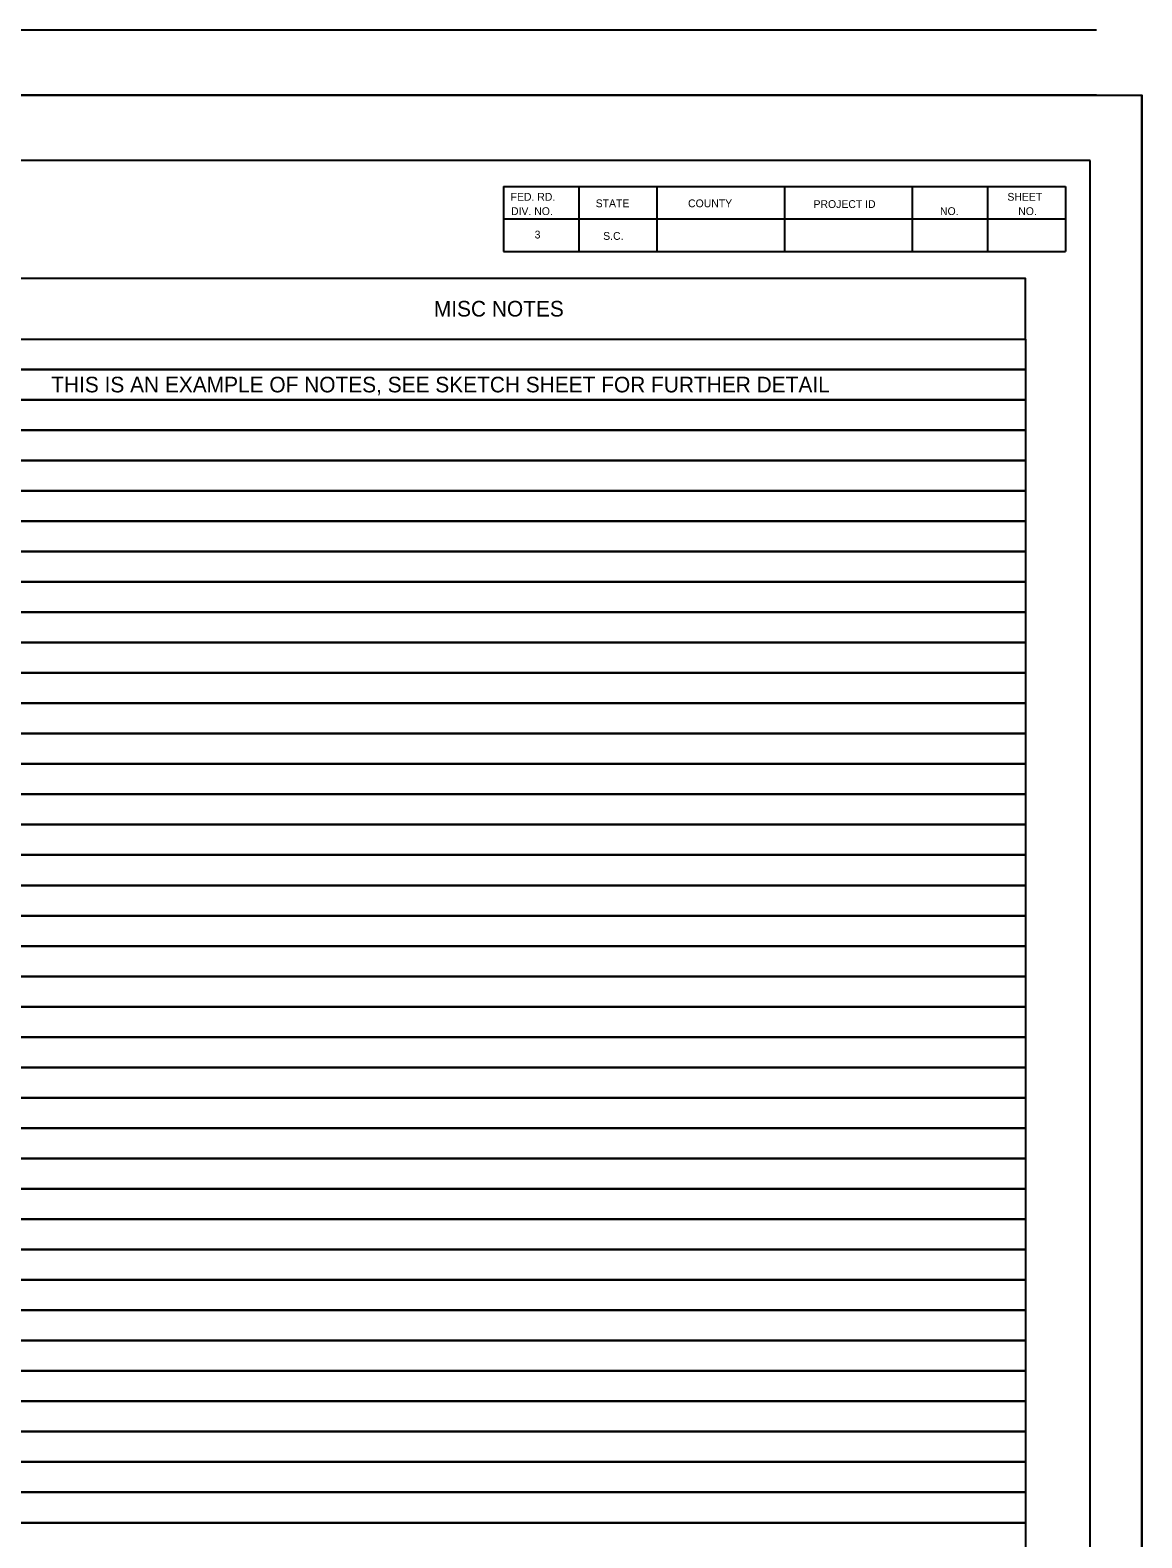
# Model space of a CAD drawing. Extents: x 14330 to 16126, y 15844 to 16994.
# Drawn here: x 15699 to 16126, y 16415 to 16994 of the extents above; entities that cross this region are included whole.
import ezdxf

# ---------------------------------------------------------------- set-up
doc = ezdxf.new("R2010")
doc.units = 0
for name, color, linetype in [('RD_SHT_Bndy', 7, 'Continuous'), ('RD_SHT_Iplotshp', 7, 'Continuous'), ('RD_SHT_Snap', 7, 'Continuous'), ('RD_SHT_TX', 7, 'Continuous')]:
    doc.layers.add(name, color=color, linetype=linetype)

msp = doc.modelspace()

# ---------------------------------------------------------------- linework, layer by layer
at = {"layer": 'RD_SHT_Bndy'}
for p, q in [((16108.25, 16993.63), (14348.25, 16993.63)), ((16108.25, 16968.63), (14348.25, 16968.63)), ((16105.85, 16943.63), (14430.85, 16943.63)), ((16105.85, 15893.63), (16105.85, 16943.63)), ((15880.35, 16933.63), (15880.35, 16908.63)), ((15880.35, 16933.63), (16037.35, 16933.63)), ((15909.35, 16933.63), (15909.35, 16908.63)), ((15939.35, 16933.63), (15939.35, 16908.63)), ((15988.35, 16933.63), (15988.35, 16908.63)), ((16037.35, 16933.63), (16037.35, 16908.63)), ((16037.35, 16933.63), (16096.35, 16933.63)), ((16066.35, 16933.63), (16066.35, 16908.63)), ((16096.35, 16933.63), (16096.35, 16908.63)), ((15880.35, 16921.13), (16037.35, 16921.13)), ((16037.35, 16921.13), (16096.35, 16921.13)), ((15880.35, 16908.63), (16037.35, 16908.63)), ((16037.35, 16908.63), (16096.35, 16908.63))]:
    msp.add_line(p, q, dxfattribs=at)
for points in [[(15676.58, 16875.02), (16080.93, 16875.02), (16080.93, 16898.3), (15676.58, 16898.3)], [(16080.93, 16863.36), (15676.58, 16863.36), (15676.58, 16875.02), (16080.93, 16875.02)], [(16080.93, 16851.71), (15676.58, 16851.71), (15676.58, 16863.36), (16080.93, 16863.36)], [(16080.93, 16840.05), (15676.58, 16840.05), (15676.58, 16851.71), (16080.93, 16851.71)], [(16080.93, 16828.4), (15676.58, 16828.4), (15676.58, 16840.05), (16080.93, 16840.05)], [(16080.93, 16816.74), (15676.58, 16816.74), (15676.58, 16828.4), (16080.93, 16828.4)], [(16080.93, 16805.09), (15676.58, 16805.09), (15676.58, 16816.74), (16080.93, 16816.74)], [(16080.93, 16793.43), (15676.58, 16793.43), (15676.58, 16805.09), (16080.93, 16805.09)], [(16080.93, 16781.78), (15676.58, 16781.78), (15676.58, 16793.43), (16080.93, 16793.43)], [(16080.93, 16770.12), (15676.58, 16770.12), (15676.58, 16781.78), (16080.93, 16781.78)], [(16080.93, 16758.47), (15676.58, 16758.47), (15676.58, 16770.12), (16080.93, 16770.12)], [(16080.93, 16746.81), (15676.58, 16746.81), (15676.58, 16758.47), (16080.93, 16758.47)], [(16080.93, 16735.16), (15676.58, 16735.16), (15676.58, 16746.81), (16080.93, 16746.81)], [(16080.93, 16723.5), (15676.58, 16723.5), (15676.58, 16735.16), (16080.93, 16735.16)], [(16080.93, 16711.84), (15676.58, 16711.84), (15676.58, 16723.5), (16080.93, 16723.5)], [(16080.93, 16700.19), (15676.58, 16700.19), (15676.58, 16711.84), (16080.93, 16711.84)], [(16080.93, 16688.53), (15676.58, 16688.53), (15676.58, 16700.19), (16080.93, 16700.19)], [(16080.93, 16676.88), (15676.58, 16676.88), (15676.58, 16688.53), (16080.93, 16688.53)], [(16080.93, 16665.22), (15676.58, 16665.22), (15676.58, 16676.88), (16080.93, 16676.88)], [(16080.93, 16653.57), (15676.58, 16653.57), (15676.58, 16665.22), (16080.93, 16665.22)], [(16080.93, 16641.91), (15676.58, 16641.91), (15676.58, 16653.57), (16080.93, 16653.57)], [(16080.93, 16630.26), (15676.58, 16630.26), (15676.58, 16641.91), (16080.93, 16641.91)], [(16080.93, 16618.6), (15676.58, 16618.6), (15676.58, 16630.26), (16080.93, 16630.26)], [(16080.93, 16606.95), (15676.58, 16606.95), (15676.58, 16618.6), (16080.93, 16618.6)], [(16080.93, 16595.29), (15676.58, 16595.29), (15676.58, 16606.95), (16080.93, 16606.95)], [(16080.93, 16583.64), (15676.58, 16583.64), (15676.58, 16595.29), (16080.93, 16595.29)], [(16080.93, 16571.98), (15676.58, 16571.98), (15676.58, 16583.64), (16080.93, 16583.64)], [(16080.93, 16560.33), (15676.58, 16560.33), (15676.58, 16571.98), (16080.93, 16571.98)], [(16080.93, 16548.67), (15676.58, 16548.67), (15676.58, 16560.33), (16080.93, 16560.33)], [(16080.93, 16537.02), (15676.58, 16537.02), (15676.58, 16548.67), (16080.93, 16548.67)], [(16080.93, 16525.36), (15676.58, 16525.36), (15676.58, 16537.02), (16080.93, 16537.02)], [(16080.93, 16513.71), (15676.58, 16513.71), (15676.58, 16525.36), (16080.93, 16525.36)], [(16080.93, 16502.05), (15676.58, 16502.05), (15676.58, 16513.71), (16080.93, 16513.71)], [(16080.93, 16490.4), (15676.58, 16490.4), (15676.58, 16502.05), (16080.93, 16502.05)], [(16080.93, 16478.74), (15676.58, 16478.74), (15676.58, 16490.4), (16080.93, 16490.4)], [(16080.93, 16467.09), (15676.58, 16467.09), (15676.58, 16478.74), (16080.93, 16478.74)], [(16080.93, 16455.43), (15676.58, 16455.43), (15676.58, 16467.09), (16080.93, 16467.09)], [(16080.93, 16443.78), (15676.58, 16443.78), (15676.58, 16455.43), (16080.93, 16455.43)], [(16080.93, 16432.12), (15676.58, 16432.12), (15676.58, 16443.78), (16080.93, 16443.78)], [(16080.93, 16420.46), (15676.58, 16420.46), (15676.58, 16432.12), (16080.93, 16432.12)], [(16080.93, 16408.81), (15676.58, 16408.81), (15676.58, 16420.46), (16080.93, 16420.46)]]:
    msp.add_lwpolyline(points, close=True, dxfattribs=at)
at = {"layer": 'RD_SHT_Iplotshp'}
msp.add_lwpolyline([(14329.65, 16968.63), (16125.65, 16968.63), (16125.65, 15868.63), (14329.65, 15868.63)], close=True, dxfattribs=at)
at = {"layer": 'RD_SHT_Snap'}
msp.add_line((16125.65, 15868.63), (16125.65, 16968.63), dxfattribs=at)

# ---------------------------------------------------------------- texts
at = {"layer": 'RD_SHT_TX'}
for s, height, p in [('FED. RD.', 3, (15883.11, 16928.13)), ('SHEET', 3, (16074, 16928.13)), ('DIV. NO.', 3, (15883.27, 16922.63)), ('STATE', 3, (15915.8, 16925.63)), ('COUNTY', 3, (15951.3, 16925.63)), ('PROJECT ID', 3, (15999.49, 16925.34)), ('NO.', 3, (16048.1, 16922.63)), ('NO.', 3, (16078.15, 16922.63)), ('3', 3, (15892.35, 16913.63)), ('S.C.', 3, (15918.69, 16913.11)), ('MISC NOTES', 6, (15853.62, 16883.66)), ('THIS IS AN EXAMPLE OF NOTES, SEE SKETCH SHEET FOR FURTHER DETAIL', 6, (15706.6, 16854.53))]:
    msp.add_text(s, height=height, dxfattribs=at).set_placement(p)

doc.saveas('drawing.dxf')
